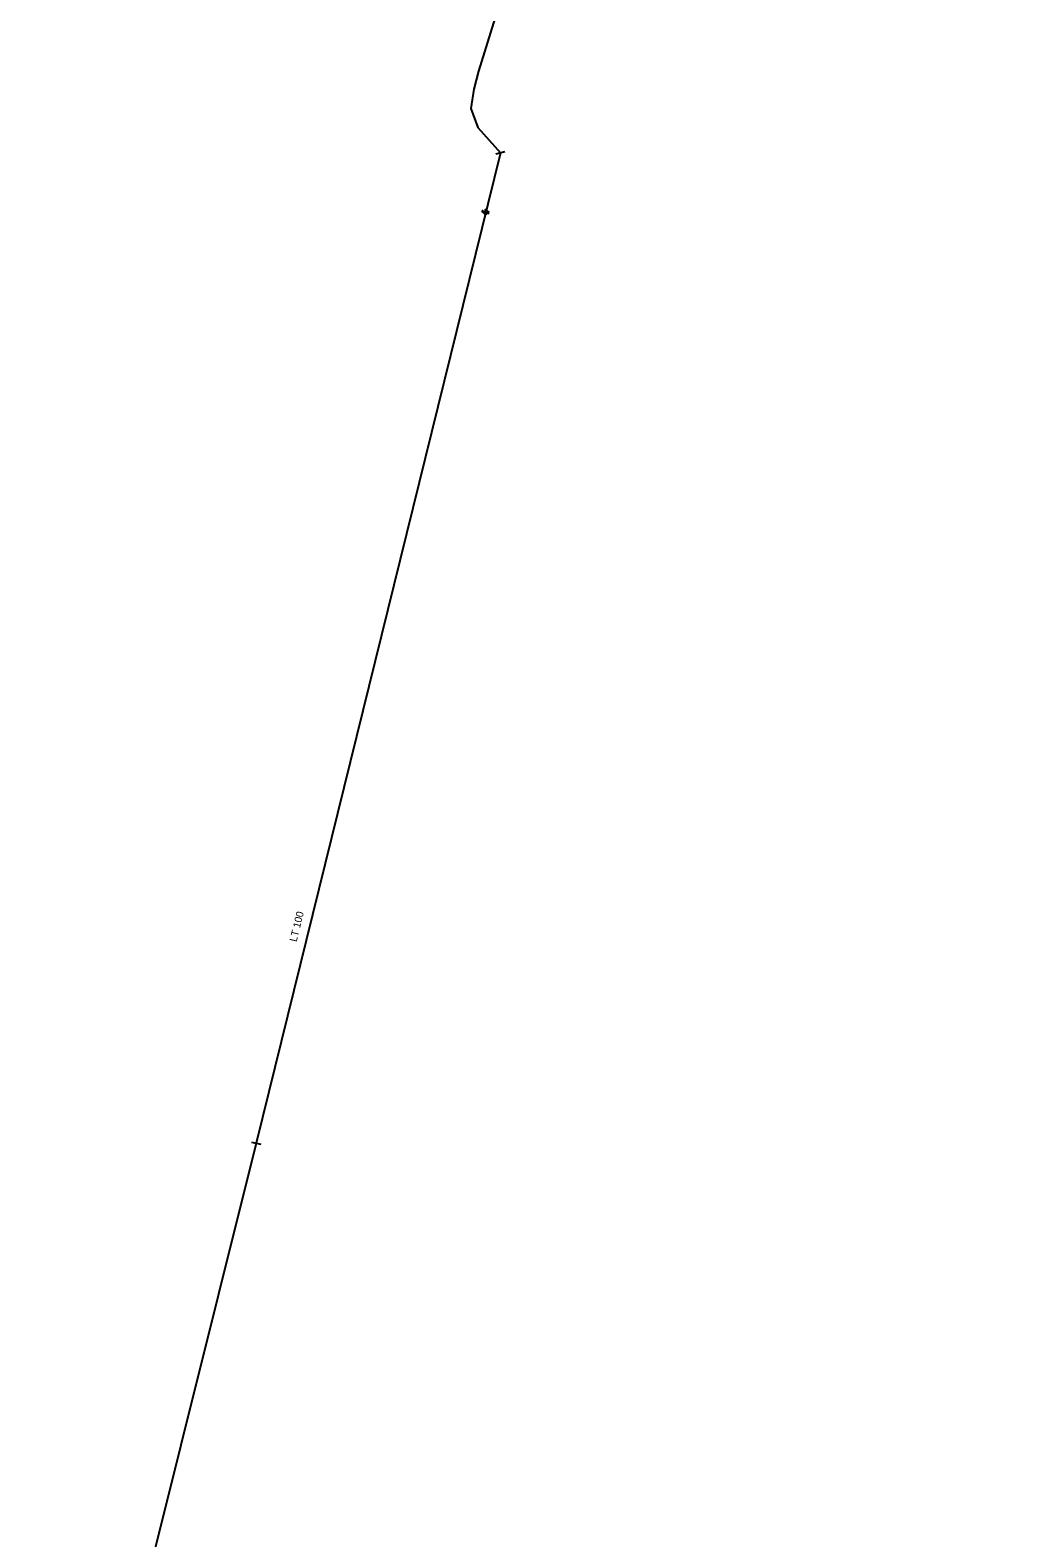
# Model space of a CAD drawing. Extents: x -867696 to -865033, y -1042522 to -1039817.
# Drawn here: x -865486.4 to -865218.1, y -1041592.7 to -1041184.7 of the extents above; entities that cross this region are included whole.
import ezdxf

# ---------------------------------------------------------------- set-up
doc = ezdxf.new("R2010")
doc.units = 0
for name, color, linetype in [('Level 1', 7, 'Continuous'), ('V - armatura', 7, 'Continuous'), ('V - ostatni', 7, 'Continuous'), ('V - popis material', 7, 'Continuous'), ('V - rozvadeci', 7, 'Continuous')]:
    doc.layers.add(name, color=color, linetype=linetype)

# ---------------------------------------------------------------- blocks, each defined once
blk = doc.blocks.new('147')
at = {"layer": 'Level 1'}
blk.add_line((0, 1.27), (0, -1.27), dxfattribs=at)
blk = doc.blocks.new('156')
at = {"layer": 'Level 1'}
for p, q in [((-0.07, 1.04), (-0.68, -0.3)), ((0.28, 1.04), (-0.19, 0.08)), ((-0.19, 0.08), (0.7, 0.29)), ((0.7, 0.29), (0.02, -1.08)), ((-0.68, -0.3), (0.21, -0.09)), ((0.21, -0.09), (-0.28, -1.08))]:
    blk.add_line(p, q, dxfattribs=at)

msp = doc.modelspace()

# ---------------------------------------------------------------- linework, layer by layer
at = {"layer": 'V - rozvadeci'}
for points in [[(-865218.08, -1040789.44), (-865221.302, -1040790.746), (-865242.12, -1040799.77), (-865254.24, -1040805.3), (-865256.14, -1040810.11), (-865249.4, -1040837.49), (-865253.1, -1040842.97), (-865287.39, -1040876.73), (-865288.71, -1040885.55), (-865292.82, -1040907.3), (-865299.09, -1040929.21), (-865304.16, -1040948.97), (-865313.2, -1040983.18), (-865320.84, -1041015.47), (-865330.84, -1041057.71), (-865337.42, -1041087.21), (-865345.33, -1041121.67), (-865351.4, -1041149.61), (-865359.29, -1041177.45), (-865364.92, -1041195.75), (-865366.18, -1041200.61), (-865367.07, -1041205.82), (-865365.16, -1041210.96), (-865359.01, -1041217.82)], [(-865359.01, -1041217.82), (-865425.167, -1041485.894)], [(-865425.167, -1041485.894), (-865486.37, -1041731.094)]]:
    msp.add_lwpolyline(points, dxfattribs=at)

# ---------------------------------------------------------------- block references
at = {"layer": 'V - armatura'}
for p, xscale, yscale, rotation in [((-865359.01, -1041217.82), 0.999999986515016, 0.9999999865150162, 105.00000012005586), ((-865425.167, -1041485.894), 0.9999999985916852, 0.9999999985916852, 76.99999972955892)]:
    msp.add_blockref('147', p, dxfattribs=dict(at, xscale=xscale, yscale=yscale, rotation=rotation))
at = {"layer": 'V - ostatni', "xscale": 0.9999999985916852, "yscale": 0.9999999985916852, "rotation": -103.00000027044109}
msp.add_blockref('156', (-865362.971, -1041233.87), dxfattribs=at)

# ---------------------------------------------------------------- texts
at = {"layer": 'V - popis material'}
msp.add_text('LT 100', height=2, rotation=76.14, dxfattribs=at).set_placement((-865414.222, -1041431.526))

doc.saveas('drawing.dxf')
